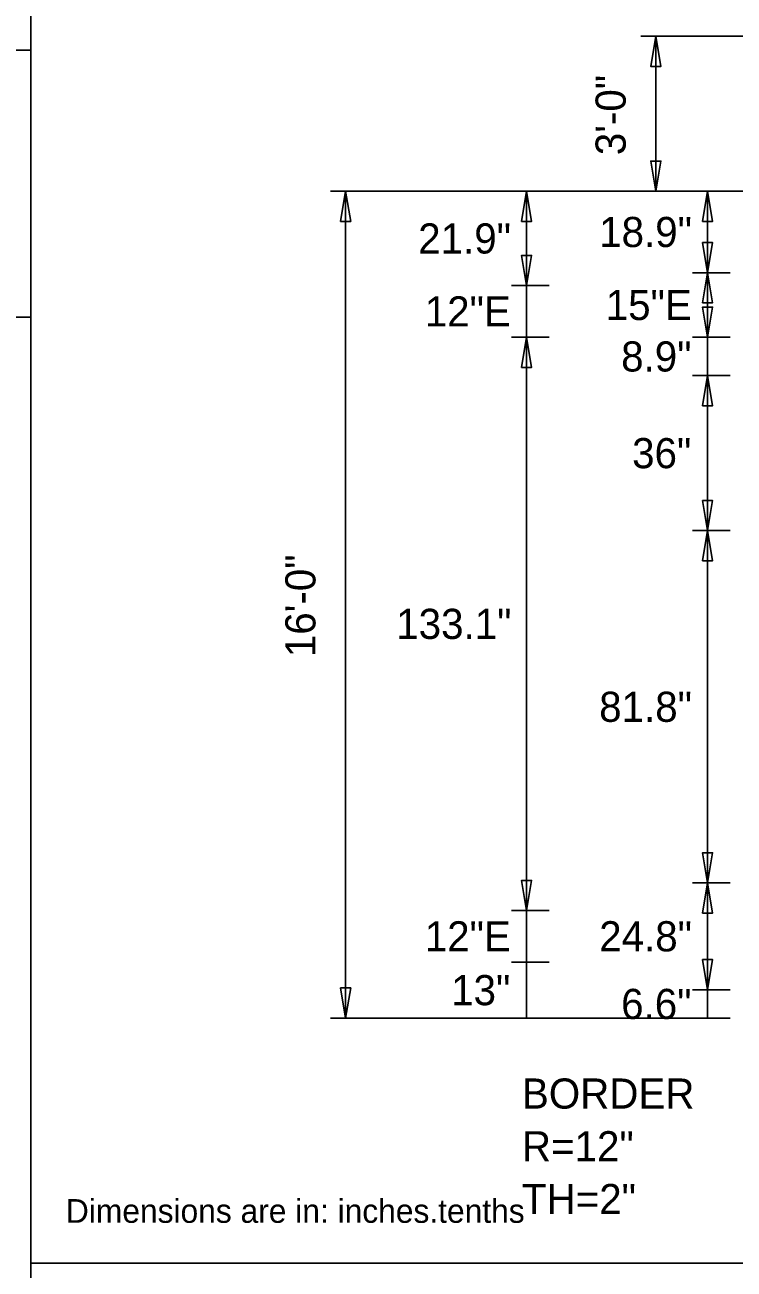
# Model space of a CAD drawing. Extents: x 2149934 to 2150188, y 145114 to 145238.
# Drawn here: x 2150076.2 to 2150089.92, y 145143.36 to 145167.44 of the extents above; entities that cross this region are included whole.
import ezdxf

# ---------------------------------------------------------------- set-up
doc = ezdxf.new("R2010")
doc.units = 0
doc.layers.add('GSDIMS', color=7, linetype='Continuous')
doc.layers.add('Level 1', color=7, linetype='Continuous')

msp = doc.modelspace()

# ---------------------------------------------------------------- linework, layer by layer
at = {"layer": 'GSDIMS'}
for p, q in [((2150088.841, 145167.217), (2150088.112, 145167.217)), ((2150088.403, 145164.216), (2150088.403, 145167.217)), ((2150092.341, 145167.217), (2150088.841, 145167.217)), ((2150082.841, 145164.216), (2150082.112, 145164.216)), ((2150082.404, 145148.216), (2150082.404, 145164.216)), ((2150089.841, 145164.216), (2150082.841, 145164.216)), ((2150086.341, 145164.216), (2150085.612, 145164.216)), ((2150085.904, 145162.391), (2150085.904, 145164.216)), ((2150088.841, 145164.216), (2150088.112, 145164.216)), ((2150092.341, 145164.216), (2150088.841, 145164.216)), ((2150089.841, 145164.216), (2150089.112, 145164.216)), ((2150089.404, 145162.641), (2150089.404, 145164.216)), ((2150089.841, 145162.641), (2150089.112, 145162.641)), ((2150089.841, 145162.641), (2150089.112, 145162.641)), ((2150089.404, 145162.641), (2150089.404, 145161.391)), ((2150086.341, 145162.391), (2150085.612, 145162.391)), ((2150086.341, 145162.391), (2150085.612, 145162.391)), ((2150085.904, 145162.391), (2150085.904, 145161.391)), ((2150086.341, 145161.391), (2150085.612, 145161.391)), ((2150086.341, 145161.391), (2150085.612, 145161.391)), ((2150085.904, 145150.3), (2150085.904, 145161.391)), ((2150089.841, 145161.391), (2150089.112, 145161.391)), ((2150089.841, 145161.391), (2150089.112, 145161.391)), ((2150089.404, 145160.65), (2150089.404, 145161.391)), ((2150089.841, 145160.65), (2150089.112, 145160.65)), ((2150089.841, 145160.65), (2150089.112, 145160.65)), ((2150089.404, 145160.65), (2150089.404, 145157.65)), ((2150089.841, 145157.65), (2150089.112, 145157.65)), ((2150089.841, 145157.65), (2150089.112, 145157.65)), ((2150089.404, 145150.834), (2150089.404, 145157.65)), ((2150089.841, 145150.834), (2150089.112, 145150.834)), ((2150089.841, 145150.834), (2150089.112, 145150.834)), ((2150089.404, 145150.834), (2150089.404, 145148.767)), ((2150086.341, 145150.3), (2150085.612, 145150.3)), ((2150086.341, 145150.3), (2150085.612, 145150.3)), ((2150085.904, 145150.3), (2150085.904, 145149.3)), ((2150086.341, 145149.3), (2150085.612, 145149.3)), ((2150086.341, 145149.3), (2150085.612, 145149.3)), ((2150085.904, 145148.216), (2150085.904, 145149.3)), ((2150089.841, 145148.767), (2150089.112, 145148.767)), ((2150089.841, 145148.767), (2150089.112, 145148.767)), ((2150089.404, 145148.216), (2150089.404, 145148.767)), ((2150082.841, 145148.216), (2150082.112, 145148.216)), ((2150089.841, 145148.216), (2150082.841, 145148.216)), ((2150086.341, 145148.216), (2150085.612, 145148.216)), ((2150089.841, 145148.216), (2150089.112, 145148.216))]:
    msp.add_line(p, q, dxfattribs=at)
for points in [[(2150088.403, 145167.217), (2150088.5, 145166.634), (2150088.306, 145166.634)], [(2150088.403, 145164.216), (2150088.5, 145164.8), (2150088.306, 145164.8)], [(2150082.404, 145164.216), (2150082.501, 145163.633), (2150082.306, 145163.633)], [(2150085.904, 145164.216), (2150086.001, 145163.633), (2150085.806, 145163.633)], [(2150089.404, 145164.216), (2150089.501, 145163.633), (2150089.306, 145163.633)], [(2150089.404, 145162.641), (2150089.501, 145163.225), (2150089.306, 145163.225)], [(2150085.904, 145162.391), (2150086.001, 145162.975), (2150085.806, 145162.975)], [(2150089.404, 145162.641), (2150089.501, 145162.058), (2150089.306, 145162.058)], [(2150089.404, 145161.391), (2150089.501, 145161.975), (2150089.306, 145161.975)], [(2150085.904, 145161.391), (2150086.001, 145160.808), (2150085.806, 145160.808)], [(2150089.404, 145160.65), (2150089.501, 145160.066), (2150089.306, 145160.066)], [(2150089.404, 145157.65), (2150089.501, 145158.233), (2150089.306, 145158.233)], [(2150089.404, 145157.65), (2150089.501, 145157.066), (2150089.306, 145157.066)], [(2150089.404, 145150.834), (2150089.501, 145151.417), (2150089.306, 145151.417)], [(2150085.904, 145150.3), (2150086.001, 145150.883), (2150085.806, 145150.883)], [(2150089.404, 145150.834), (2150089.501, 145150.25), (2150089.306, 145150.25)], [(2150089.404, 145148.767), (2150089.501, 145149.35), (2150089.306, 145149.35)], [(2150082.404, 145148.216), (2150082.501, 145148.8), (2150082.306, 145148.8)]]:
    msp.add_lwpolyline(points, close=True, dxfattribs=at)
at = {"layer": 'Level 1'}
for p, q in [((2150076.316, 145216.512), (2150076.316, 145117.388)), ((2150076.316, 145166.95), (2150017.557, 145166.95)), ((2150062.21, 145161.778), (2150076.316, 145161.778)), ((2150076.316, 145143.476), (2150121.342, 145143.476))]:
    msp.add_line(p, q, dxfattribs=at)

# ---------------------------------------------------------------- texts
at = {"layer": 'GSDIMS'}
for s, p in [('3\'-0"', (2150087.82, 145164.915)), ('16\'-0"', (2150081.82, 145155.202))]:
    msp.add_text(s, height=0.5833, rotation=90, dxfattribs=at).set_placement(p)
for s, p in [('21.9"', (2150083.807, 145163.012)), ('18.9"', (2150087.307, 145163.137)), ('12"E', (2150083.934, 145161.6)), ('15"E', (2150087.434, 145161.725)), ('8.9"', (2150087.732, 145160.729)), ('36"', (2150087.944, 145158.858)), ('133.1"', (2150083.382, 145155.554)), ('81.8"', (2150087.307, 145153.95)), ('12"E', (2150083.934, 145149.508)), ('24.8"', (2150087.307, 145149.509)), ('13"', (2150084.444, 145148.467)), ('6.6"', (2150087.732, 145148.2)), ('BORDER', (2150085.813, 145146.466)), ('R=12"', (2150085.813, 145145.446)), ('TH=2"', (2150085.813, 145144.425))]:
    msp.add_text(s, height=0.5833, dxfattribs=at).set_placement(p)
at = {"layer": 'Level 1'}
msp.add_text('Dimensions are in: inches.tenths', height=0.45913, dxfattribs=at).set_placement((2150076.993, 145144.256))

doc.saveas('drawing.dxf')
